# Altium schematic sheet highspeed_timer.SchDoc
size A3
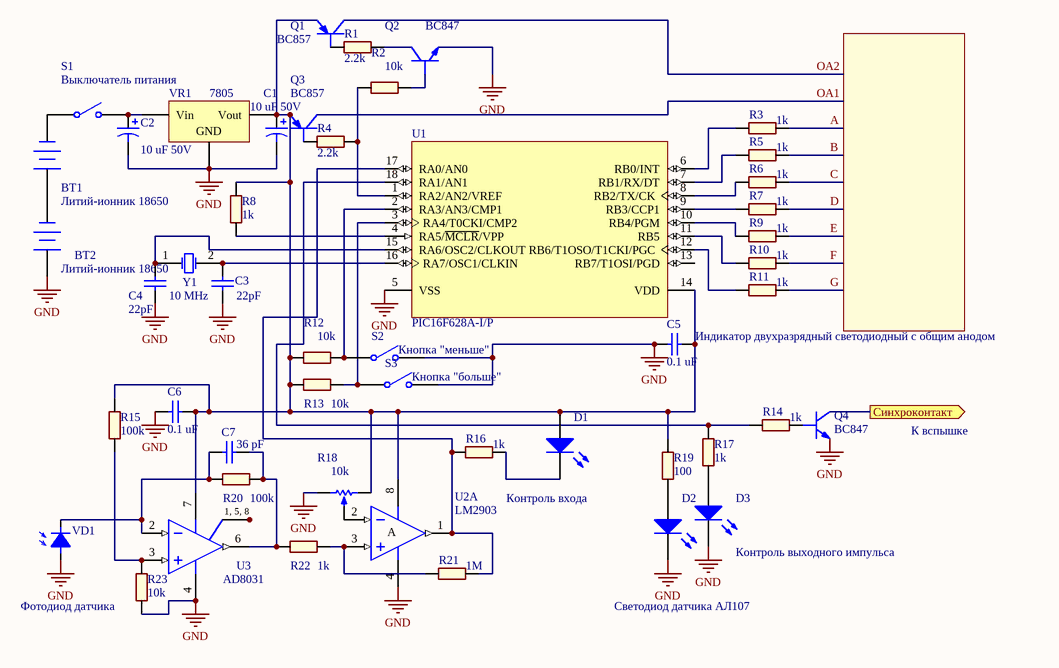
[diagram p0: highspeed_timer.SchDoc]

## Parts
BT1  Литий-ионник 18650  [BAT-2]
BT2  Литий-ионник 18650  [BAT-2]
C1  value 10 uF 50V  [C2225]
C2  value 10 uF 50V  [C2225]
C3  value 22pF  [1608[0603]]
C4  value 22pF  [1608[0603]]
C5  value 0.1 uF  [1608[0603]]
C6  value 0.1 uF  [1608[0603]]
C7  value 36 pF  [1608[0603]]
D1  Контроль входа  [3.2X1.6X1.1]
D2  Светодиод датчика АЛ107  [3.2X1.6X1.1]
D3  Контроль выходного импульса  [3.2X1.6X1.1]
Q1  BC857  [SOT-23]
Q2  BC847  [SOT-23]
Q3  BC857  [SOT-23]
Q4  BC847  [SOT-23]
R1  2.2k  [R0805]
R2  10k  [R0805]
R3  1k  [R0805]
R4  2.2k  [R0805]
R5  1k  [R0805]
R6  1k  [R0805]
R7  1k  [R0805]
R8  1k  [R0805]
R9  1k  [R0805]
R10  1k  [R0805]
R11  1k  [R0805]
R12  10k  [R0805]
R13  10k  [R0805]
R14  1k  [R0805]
R15  100k  [R0805]
R16  1k  [R0805]
R17  1k  [R0805]
R18  10k  [VR5]
R19  100  [R0805]
R20  100k  [R0805]
R21  1M  [R0805]
R22  1k  [R0805]
R23  10k  [R0805]
S1  Выключатель питания  [SPST-2]
S2  Кнопка "меньше"  [SPST-2]
S3  Кнопка "больше"  [SPST-2]
U1  PIC16F628A-I/P  [PDIP300-18]
U2  LM2903  [N-8]  (part A of 2)
U3  AD8031  [R-8D_N]
VD1  Фотодиод датчика  [BP104]
VR1  7805  [D2PAK]
Y1  10 MHz  [R38]

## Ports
Синхроконтакт (out)

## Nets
GND: BT2.1(+) C1.2 C2.2 C3.1 C4.1 C5.2 C6.1 D2.2(K) D3.2(K) Q2.2(E) Q4.2(E) R18.1(TOP) R23.2 S2.2(NO) S3.2(NO) U1.5(VSS) U2.4(V-) U3.4(V-) VD1.A VR1.2(GND)
A: R3.1
B: R5.1
C: R6.1
D: R7.1
E: R9.1
F: R10.1
G : R11.1
OA1: Q3.3(C)
OA2: Q1.3(C)
Синхроконтакт: Q4.3(C) ; port Синхроконтакт
NetBT1_1: BT1.1(+) BT2.2(-)
NetBT1_2: BT1.2(-) S1.1(COMMON)
NetC1_1: C1.1 C5.1 C6.2 D1.1(A) Q1.2(E) Q3.2(E) R8.1 R12.1 R13.1 R15.1 R18.2(BOT) R19.1 U1.14(VDD) U2.8(V+) U3.7(V+) VR1.3(Vout)
NetC2_1: C2.1 S1.2(NO) VR1.1(Vin)
NetC3_2: C3.2 U1.16(RA7/OSC1/CLKIN) Y1.2(OSC2)
NetC4_2: C4.2 U1.15(RA6/OSC2/CLKOUT) Y1.1(OSC1)
NetC7_1: C7.1 R20.2 R22.2 U3.6(OUT)
NetC7_2: C7.2 R20.1 U3.2(IN-) VD1.C
NetD1_2: D1.2(K) R16.1
NetD2_1: D2.1(A) R19.2
NetD3_1: D3.1(A) R17.2
NetQ1_1: Q1.1(B) R1.1
NetQ2_1: Q2.1(B) R2.2
NetQ2_3: Q2.3(C) R1.2
NetQ3_1: Q3.1(B) R4.1
NetQ4_1: Q4.1(B) R14.1
NetR2_1: R2.1 R4.2 U1.1(RA2/AN2/VREF)
NetR3_2: R3.2 U1.6(RB0/INT)
NetR5_2: R5.2 U1.7(RB1/RX/DT)
NetR6_2: R6.2 U1.8(RB2/TX/CK)
NetR7_2: R7.2 U1.9(RB3/CCP1)
NetR8_2: R8.2 U1.4(RA5/~{MCLR}/VPP)
NetR9_2: R9.2 U1.10(RB4/PGM)
NetR10_2: R10.2 U1.11(RB5)
NetR11_2: R11.2 U1.12(RB6/T1OSO/T1CKI/PGC)
NetR12_2: R12.2 S2.1(COMMON) U1.2(RA3/AN3/CMP1)
NetR13_2: R13.2 S3.1(COMMON) U1.3(RA4/T0CKI/CMP2)
NetR14_2: R14.2 R17.1 U1.18(RA1/AN1)
NetR15_2: R15.2 R23.1 U3.3(IN+)
NetR16_2: R16.2 R21.1 U1.17(RA0/AN0) U2.1(OUT)
NetR18_3: R18.3(TAP) U2.2(IN-)
NetR21_2: R21.2 R22.1 U2.3(IN+)
NetU3_1: U3.1(NC) U3.5(NC) U3.8(NC)

Not connected (* = marked no-connect by the designer): U1 13(RB7/T1OSI/PGD)

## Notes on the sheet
- (near C5) Индикатор двухразрядный светодиодный с общим анодом
- К вспышке

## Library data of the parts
BT1 BT2 = Battery: Multicell Battery
C1 C2 = Cap Pol3: Polarized Capacitor (Surface Mount)
C3-C7 = Cap Semi: Capacitor (Semiconductor SIM Model)
D1-D3 = LED2: Typical RED, GREEN, YELLOW, AMBER GaAs LED
R1-R17 R19-R23 = R-0805: Chip resistor 0805; Power: 0.125; Tolerance: 5%; Value: val; Voltage: 150V
R18 = RPot: Potentiometer; Sim Note: Enter the Resistance value and the set point into parameter fields.; Set Position: 0.5
S1-S3 = SW-SPST: Single-Pole, Single-Throw Switch
U1 = PIC16F628A-I/P: FLASH-Based 8-Bit CMOS Microcontroller with nanoWatt Technology, 2K (x14-Bit words) FLASH, 224 Bytes SRAM, 18-Pin PDIP, 3.0 to 5.5V Supply Range, Industrial Temperature
U2 = AD822AN: Single-Supply, Rail-to-Rail Low-Power FET-Input Operational Amplifier
U3 = AD820AR-3V: Single-Supply, Rail-to-Rail Low-Power FET-Input Operational Amplifier; Note: Pins 1, 5 and 8 are not connected.
VD1 = BP104: PHOTODIODE PIN TOP VIEW 2-DIP; Manufacturer: Vishay Semiconductors; Active Area: 7.5mm?; Spectral Range: 870nm ~ 1050nm; Current - Dark (Typ): 2nA; Voltage - DC Reverse (Vr) (Max): 60V; Wavelength: 950nm
VR1 = Volt Reg: Voltage Regulator
Y1 = XTAL: Crystal Oscillator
